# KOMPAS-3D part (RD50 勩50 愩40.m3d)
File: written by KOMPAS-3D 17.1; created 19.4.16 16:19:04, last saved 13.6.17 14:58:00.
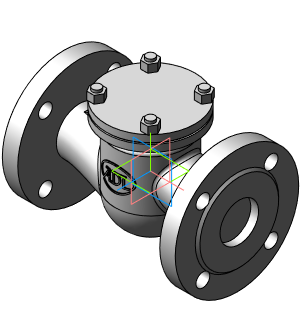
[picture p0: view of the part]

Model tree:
1. Операция без истории:2  (labels: Сталь 20  ГОСТ 1050-88)

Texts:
  RD50 Ду15 Ру40
  RD50 Ду20 Ру40
  RD50 Ду25 Ру40
  RD50 Ду32 Ру40
  RD50 Ду40 Ру40
  RD50 Ду50 Ру40
  RD50 Ду65 Ру40
  RD50 Ду80 Ру40
  RD50 Ду100 Ру40
  RD50 Ду125 Ру40
  RD50 Ду150 Ру40
  RD50 Ду200 Ру40
  RD50 Ду250 Ру40
  RD50 Ду300 Ру40
  RD50 Ду350 Ру40
  RD50 Ду400 Ру40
